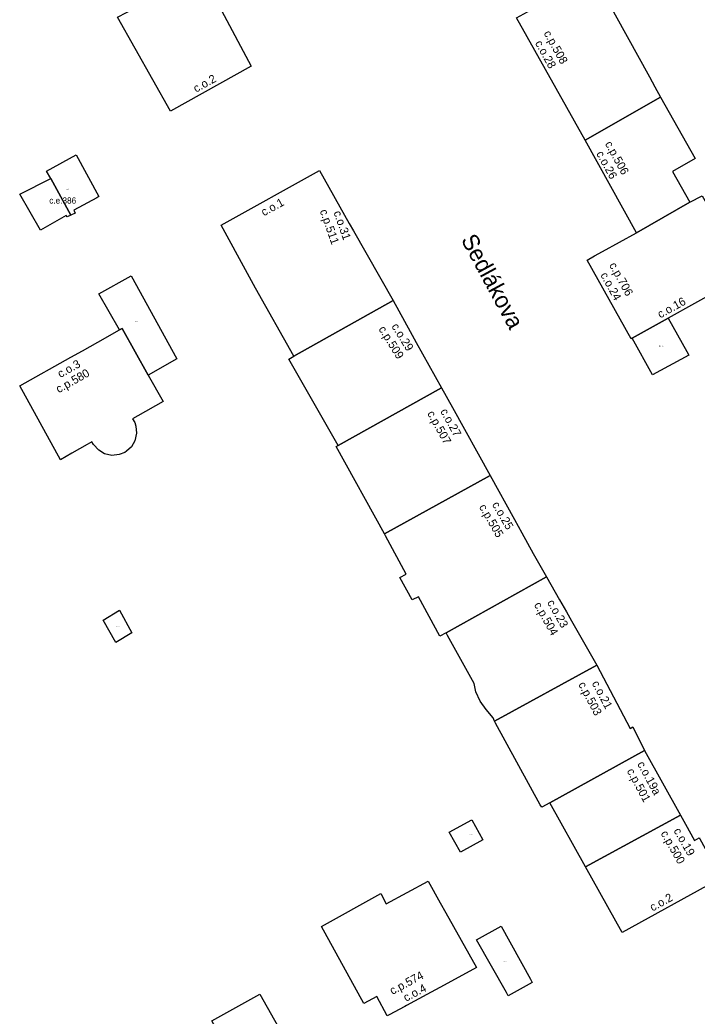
# Model space of a CAD drawing. Extents: x -600391 to -599491, y -1160176 to -1159402.
# Drawn here: x -600308.5 to -600226.8, y -1159941 to -1159820.9 of the extents above; entities that cross this region are included whole.
import ezdxf

# ---------------------------------------------------------------- set-up
doc = ezdxf.new("R2010")
doc.units = 0
for name, color, linetype in [('Level 10', 7, 'Continuous'), ('Level 11', 7, 'Continuous'), ('Level 12', 7, 'Continuous'), ('Level 23', 7, 'Continuous'), ('Level 24', 7, 'Continuous'), ('Level 25', 7, 'Continuous'), ('Level 61', 7, 'Continuous'), ('Level 62', 7, 'Continuous')]:
    doc.layers.add(name, color=color, linetype=linetype)

msp = doc.modelspace()

# ---------------------------------------------------------------- linework, layer by layer
at = {"layer": 'Level 61'}
for points in [[(-600237.94, -1159818), (-600232.57, -1159827.75)], [(-600284.2, -1159819.76), (-600280.6, -1159826.47)], [(-600290.35, -1159831.88), (-600296.72, -1159820.57)], [(-600240.34, -1159835.38), (-600248.62, -1159820.62)], [(-600280.6, -1159826.47), (-600290.35, -1159831.88)], [(-600232.57, -1159827.75), (-600231.9, -1159828.97)], [(-600231.9, -1159828.97), (-600231.22, -1159830.2)], [(-600240.34, -1159835.38), (-600231.22, -1159830.2)], [(-600231.22, -1159830.2), (-600240.34, -1159835.38)], [(-600231.22, -1159830.2), (-600227.07, -1159837.62)], [(-600234.14, -1159846.56), (-600240.34, -1159835.38)], [(-600305.31, -1159839.13), (-600301.74, -1159837.17)], [(-600301.74, -1159837.17), (-600298.98, -1159842.18)], [(-600227.07, -1159837.62), (-600229.77, -1159839.19)], [(-600304.8, -1159840.02), (-600305.31, -1159839.13)], [(-600284.24, -1159845.64), (-600272.36, -1159839.07)], [(-600272.36, -1159839.07), (-600268.78, -1159845.46)], [(-600308.51, -1159841.92), (-600304.8, -1159840.02)], [(-600304.8, -1159840.02), (-600302.38, -1159844.42)], [(-600302.38, -1159844.42), (-600304.8, -1159840.02)], [(-600229.77, -1159839.19), (-600227.68, -1159842.88)], [(-600306.03, -1159846.25), (-600308.51, -1159841.92)], [(-600299.25, -1159842.33), (-600302.02, -1159843.85)], [(-600298.98, -1159842.18), (-600299.25, -1159842.33)], [(-600227.68, -1159842.88), (-600226.21, -1159842.09)], [(-600302.02, -1159843.85), (-600301.86, -1159844.18)], [(-600227.68, -1159842.88), (-600234.14, -1159846.56)], [(-600234.14, -1159846.56), (-600227.68, -1159842.88)], [(-600302.92, -1159844.47), (-600305.73, -1159846.08)], [(-600302.81, -1159844.66), (-600302.92, -1159844.47)], [(-600302.38, -1159844.42), (-600302.81, -1159844.66)], [(-600301.86, -1159844.18), (-600302.38, -1159844.42)], [(-600305.73, -1159846.08), (-600306.03, -1159846.25)], [(-600281.06, -1159851.49), (-600284.24, -1159845.64)], [(-600268.78, -1159845.46), (-600268.28, -1159846.34)], [(-600268.28, -1159846.34), (-600263.49, -1159854.75)], [(-600238.23, -1159848.83), (-600234.14, -1159846.56)], [(-600240.09, -1159849.86), (-600239.19, -1159849.36)], [(-600234.77, -1159859.35), (-600240.09, -1159849.86)], [(-600239.19, -1159849.36), (-600238.23, -1159848.83)], [(-600298.99, -1159853.92), (-600295.08, -1159851.74)], [(-600295.08, -1159851.74), (-600289.57, -1159861.77)], [(-600280.09, -1159853.23), (-600281.06, -1159851.49)], [(-600220.78, -1159851.55), (-600230.3, -1159856.86)], [(-600275.48, -1159861.46), (-600280.09, -1159853.23)], [(-600296.48, -1159858.28), (-600298.99, -1159853.92)], [(-600263.49, -1159854.75), (-600275.48, -1159861.46)], [(-600275.48, -1159861.46), (-600263.49, -1159854.75)], [(-600263.49, -1159854.75), (-600261.42, -1159858.49)], [(-600234.65, -1159859.28), (-600230.3, -1159856.86)], [(-600230.3, -1159856.86), (-600234.65, -1159859.28)], [(-600230.3, -1159856.86), (-600228.06, -1159860.88)], [(-600299.11, -1159859.76), (-600296.48, -1159858.28)], [(-600296.48, -1159858.28), (-600296.16, -1159858.1)], [(-600296.16, -1159858.1), (-600296.48, -1159858.28)], [(-600296.16, -1159858.1), (-600293.02, -1159863.72)], [(-600293.02, -1159863.72), (-600296.16, -1159858.1)], [(-600261.42, -1159858.49), (-600260.69, -1159859.8)], [(-600234.65, -1159859.28), (-600234.77, -1159859.35)], [(-600232.19, -1159863.71), (-600234.65, -1159859.28)], [(-600302.35, -1159861.58), (-600300.95, -1159860.79)], [(-600300.95, -1159860.79), (-600299.11, -1159859.76)], [(-600260.69, -1159859.8), (-600257.67, -1159865.25)], [(-600308.51, -1159865.04), (-600302.35, -1159861.58)], [(-600289.57, -1159861.77), (-600293.02, -1159863.72)], [(-600276.06, -1159861.79), (-600275.48, -1159861.46)], [(-600270.12, -1159872.22), (-600276.06, -1159861.79)], [(-600227.82, -1159861.32), (-600232.19, -1159863.71)], [(-600228.06, -1159860.88), (-600227.82, -1159861.32)], [(-600293.02, -1159863.72), (-600291.24, -1159866.92)], [(-600303.63, -1159873.93), (-600308.51, -1159865.04)], [(-600270.12, -1159872.22), (-600257.67, -1159865.25)], [(-600257.67, -1159865.25), (-600270.12, -1159872.22)], [(-600257.67, -1159865.25), (-600256.34, -1159867.64)], [(-600291.24, -1159866.92), (-600294.28, -1159868.64)], [(-600256.34, -1159867.64), (-600251.8, -1159875.84)], [(-600294.28, -1159868.64), (-600294.91, -1159869)], [(-600294.91, -1159869), (-600294.66, -1159869.44)], [(-600294.66, -1159869.44), (-600294.51, -1159869.89)], [(-600294.51, -1159869.89), (-600294.43, -1159870.74)], [(-600294.43, -1159870.74), (-600294.63, -1159871.64)], [(-600300.38, -1159872.09), (-600302.25, -1159873.15)], [(-600299.82, -1159871.78), (-600300.38, -1159872.09)], [(-600299.65, -1159872.09), (-600299.82, -1159871.78)], [(-600298.98, -1159872.8), (-600299.65, -1159872.09)], [(-600298.3, -1159873.21), (-600298.98, -1159872.8)], [(-600295.06, -1159872.37), (-600295.66, -1159872.92)], [(-600294.63, -1159871.64), (-600295.06, -1159872.37)], [(-600270.35, -1159872.34), (-600270.12, -1159872.22)], [(-600264.54, -1159882.86), (-600270.35, -1159872.34)], [(-600302.25, -1159873.15), (-600303.63, -1159873.93)], [(-600297.44, -1159873.42), (-600298.3, -1159873.21)], [(-600296.54, -1159873.32), (-600297.44, -1159873.42)], [(-600295.86, -1159873.05), (-600296.54, -1159873.32)], [(-600295.66, -1159872.92), (-600295.86, -1159873.05)], [(-600264.54, -1159882.86), (-600251.8, -1159875.84)], [(-600251.8, -1159875.84), (-600264.54, -1159882.86)], [(-600251.8, -1159875.84), (-600248.85, -1159881.15)], [(-600248.85, -1159881.15), (-600247.96, -1159882.77)], [(-600264.39, -1159883.13), (-600264.54, -1159882.86)], [(-600261.92, -1159887.73), (-600264.39, -1159883.13)], [(-600247.96, -1159882.77), (-600246.6, -1159885.23)], [(-600246.6, -1159885.23), (-600244.97, -1159888.08)], [(-600262.68, -1159888.14), (-600261.92, -1159887.73)], [(-600261.19, -1159890.85), (-600262.68, -1159888.14)], [(-600244.97, -1159888.08), (-600257.09, -1159894.8)], [(-600257.09, -1159894.8), (-600244.97, -1159888.08)], [(-600244.97, -1159888.08), (-600243.41, -1159890.82)], [(-600260.44, -1159890.48), (-600261.19, -1159890.85)], [(-600257.87, -1159895.23), (-600260.44, -1159890.48)], [(-600243.41, -1159890.82), (-600242.59, -1159892.27)], [(-600298.48, -1159893.28), (-600296.49, -1159892.09)], [(-600296.49, -1159892.09), (-600295, -1159894.82)], [(-600242.59, -1159892.27), (-600241.96, -1159893.37)], [(-600296.94, -1159895.97), (-600298.48, -1159893.28)], [(-600241.96, -1159893.37), (-600238.92, -1159898.73)], [(-600295, -1159894.82), (-600296.94, -1159895.97)], [(-600257.09, -1159894.8), (-600257.87, -1159895.23)], [(-600256.91, -1159895.14), (-600257.09, -1159894.8)], [(-600253.73, -1159900.93), (-600256.91, -1159895.14)], [(-600251.25, -1159905.47), (-600238.92, -1159898.73)], [(-600238.92, -1159898.73), (-600251.25, -1159905.47)], [(-600238.92, -1159898.73), (-600234.91, -1159906.35)], [(-600253.52, -1159901.95), (-600253.73, -1159900.93)], [(-600252.99, -1159903.07), (-600253.52, -1159901.95)], [(-600252.25, -1159904.06), (-600252.99, -1159903.07)], [(-600251.43, -1159905.08), (-600252.25, -1159904.06)], [(-600251.25, -1159905.47), (-600251.43, -1159905.08)], [(-600251.13, -1159905.7), (-600251.25, -1159905.47)], [(-600245.73, -1159915.55), (-600251.13, -1159905.7)], [(-600234.91, -1159906.35), (-600234.58, -1159906.16)], [(-600234.58, -1159906.16), (-600233.17, -1159909.02)], [(-600244.58, -1159915.32), (-600233.17, -1159909.02)], [(-600233.17, -1159909.02), (-600244.58, -1159915.32)], [(-600233.17, -1159909.02), (-600228.82, -1159916.82)], [(-600245.56, -1159915.86), (-600245.73, -1159915.55)], [(-600244.58, -1159915.32), (-600245.56, -1159915.86)], [(-600240.29, -1159923.03), (-600244.58, -1159915.32)], [(-600228.82, -1159916.82), (-600240.29, -1159923.03)], [(-600240.29, -1159923.03), (-600228.82, -1159916.82)], [(-600228.82, -1159916.82), (-600228.23, -1159917.89)], [(-600256.71, -1159918.86), (-600253.99, -1159917.36)], [(-600253.99, -1159917.36), (-600252.66, -1159919.78)], [(-600228.23, -1159917.89), (-600227.14, -1159919.85)], [(-600255.38, -1159921.28), (-600256.71, -1159918.86)], [(-600227.14, -1159919.85), (-600226.57, -1159919.54)], [(-600252.66, -1159919.78), (-600255.38, -1159921.28)], [(-600235.87, -1159930.96), (-600240.29, -1159923.03)], [(-600264.32, -1159927.49), (-600259.28, -1159924.76)], [(-600259.28, -1159924.76), (-600257.8, -1159927.4)], [(-600224.48, -1159924.68), (-600235.87, -1159930.96)], [(-600272.11, -1159930.24), (-600264.96, -1159926.24)], [(-600264.96, -1159926.24), (-600264.32, -1159927.49)], [(-600257.8, -1159927.4), (-600257.13, -1159928.59)], [(-600257.13, -1159928.59), (-600253.42, -1159935.19)], [(-600267.03, -1159939.53), (-600272.11, -1159930.24)], [(-600253.42, -1159931.83), (-600250.47, -1159930.2)], [(-600250.47, -1159930.2), (-600246.93, -1159936.58)], [(-600249.83, -1159938.19), (-600253.42, -1159931.83)], [(-600253.42, -1159935.19), (-600257.32, -1159937.3)], [(-600257.32, -1159937.3), (-600259.41, -1159938.42)], [(-600246.71, -1159936.98), (-600249.6, -1159938.59)], [(-600246.93, -1159936.58), (-600246.71, -1159936.98)], [(-600285.36, -1159941.63), (-600279.55, -1159938.41)], [(-600279.55, -1159938.41), (-600274.78, -1159946.87)], [(-600265.47, -1159938.68), (-600267.03, -1159939.53)], [(-600264.2, -1159941.01), (-600265.47, -1159938.68)], [(-600259.41, -1159938.42), (-600261.86, -1159939.75)], [(-600249.6, -1159938.59), (-600249.83, -1159938.19)], [(-600262.09, -1159939.87), (-600263.95, -1159940.87)], [(-600261.86, -1159939.75), (-600262.09, -1159939.87)], [(-600263.95, -1159940.87), (-600264.2, -1159941.01)]]:
    msp.add_lwpolyline(points, dxfattribs=at)
at = {"layer": 'Level 62'}
for points in [[(-600288.29, -1159812.37), (-600286.39, -1159815.66), (-600284.2, -1159819.76), (-600280.6, -1159826.47), (-600290.35, -1159831.88), (-600296.72, -1159820.57), (-600294.57, -1159819.44), (-600296.16, -1159816.64), (-600288.29, -1159812.37)], [(-600231.22, -1159830.2), (-600240.34, -1159835.38), (-600248.62, -1159820.62), (-600239.3, -1159815.54), (-600238.62, -1159816.77), (-600237.94, -1159818), (-600232.57, -1159827.75), (-600231.9, -1159828.97), (-600231.22, -1159830.2)], [(-600227.68, -1159842.88), (-600234.14, -1159846.56), (-600240.34, -1159835.38), (-600231.22, -1159830.2), (-600227.07, -1159837.62), (-600229.77, -1159839.19), (-600227.68, -1159842.88)], [(-600299.25, -1159842.33), (-600302.02, -1159843.85), (-600301.86, -1159844.18), (-600302.38, -1159844.42), (-600304.8, -1159840.02), (-600305.31, -1159839.13), (-600301.74, -1159837.17), (-600298.98, -1159842.18), (-600299.25, -1159842.33)], [(-600281.06, -1159851.49), (-600284.24, -1159845.64), (-600272.36, -1159839.07), (-600268.78, -1159845.46), (-600268.28, -1159846.34), (-600263.49, -1159854.75), (-600275.48, -1159861.46), (-600280.09, -1159853.23), (-600281.06, -1159851.49)], [(-600304.8, -1159840.02), (-600302.38, -1159844.42), (-600302.81, -1159844.66), (-600302.92, -1159844.47), (-600305.73, -1159846.08), (-600306.03, -1159846.25), (-600308.51, -1159841.92), (-600304.8, -1159840.02)], [(-600238.23, -1159848.83), (-600234.14, -1159846.56), (-600227.68, -1159842.88), (-600226.21, -1159842.09), (-600220.78, -1159851.55), (-600230.3, -1159856.86), (-600234.65, -1159859.28), (-600234.77, -1159859.35), (-600240.09, -1159849.86), (-600239.19, -1159849.36), (-600238.23, -1159848.83)], [(-600295.08, -1159851.74), (-600289.57, -1159861.77), (-600293.02, -1159863.72), (-600296.16, -1159858.1), (-600296.48, -1159858.28), (-600298.99, -1159853.92), (-600295.08, -1159851.74)], [(-600270.12, -1159872.22), (-600276.06, -1159861.79), (-600275.48, -1159861.46), (-600263.49, -1159854.75), (-600261.42, -1159858.49), (-600260.69, -1159859.8), (-600257.67, -1159865.25), (-600270.12, -1159872.22)], [(-600232.19, -1159863.71), (-600234.65, -1159859.28), (-600230.3, -1159856.86), (-600228.06, -1159860.88), (-600227.82, -1159861.32), (-600232.19, -1159863.71)], [(-600300.95, -1159860.79), (-600299.11, -1159859.76), (-600296.48, -1159858.28), (-600296.16, -1159858.1), (-600293.02, -1159863.72), (-600291.24, -1159866.92), (-600294.28, -1159868.64), (-600294.91, -1159869), (-600294.66, -1159869.44), (-600294.51, -1159869.89), (-600294.43, -1159870.74), (-600294.63, -1159871.64), (-600295.06, -1159872.37), (-600295.66, -1159872.92), (-600295.86, -1159873.05), (-600296.54, -1159873.32), (-600297.44, -1159873.42), (-600298.3, -1159873.21), (-600298.98, -1159872.8), (-600299.65, -1159872.09), (-600299.82, -1159871.78), (-600300.38, -1159872.09), (-600302.25, -1159873.15), (-600303.63, -1159873.93), (-600308.51, -1159865.04), (-600302.35, -1159861.58), (-600300.95, -1159860.79)], [(-600270.12, -1159872.22), (-600257.67, -1159865.25), (-600256.34, -1159867.64), (-600251.8, -1159875.84), (-600264.54, -1159882.86), (-600270.35, -1159872.34), (-600270.12, -1159872.22)], [(-600264.54, -1159882.86), (-600251.8, -1159875.84), (-600248.85, -1159881.15), (-600247.96, -1159882.77), (-600246.6, -1159885.23), (-600244.97, -1159888.08), (-600257.09, -1159894.8), (-600257.87, -1159895.23), (-600260.44, -1159890.48), (-600261.19, -1159890.85), (-600262.68, -1159888.14), (-600261.92, -1159887.73), (-600264.39, -1159883.13), (-600264.54, -1159882.86)], [(-600241.96, -1159893.37), (-600238.92, -1159898.73), (-600251.25, -1159905.47), (-600251.43, -1159905.08), (-600252.25, -1159904.06), (-600252.99, -1159903.07), (-600253.52, -1159901.95), (-600253.73, -1159900.93), (-600256.91, -1159895.14), (-600257.09, -1159894.8), (-600244.97, -1159888.08), (-600243.41, -1159890.82), (-600242.59, -1159892.27), (-600241.96, -1159893.37)], [(-600298.48, -1159893.28), (-600296.49, -1159892.09), (-600295, -1159894.82), (-600296.94, -1159895.97), (-600298.48, -1159893.28)], [(-600238.92, -1159898.73), (-600234.91, -1159906.35), (-600234.58, -1159906.16), (-600233.17, -1159909.02), (-600244.58, -1159915.32), (-600245.56, -1159915.86), (-600245.73, -1159915.55), (-600251.13, -1159905.7), (-600251.25, -1159905.47), (-600238.92, -1159898.73)], [(-600244.58, -1159915.32), (-600233.17, -1159909.02), (-600228.82, -1159916.82), (-600240.29, -1159923.03), (-600244.58, -1159915.32)], [(-600224.36, -1159923.52), (-600224.22, -1159923.77), (-600224.78, -1159924.08), (-600224.48, -1159924.68), (-600235.87, -1159930.96), (-600240.29, -1159923.03), (-600228.82, -1159916.82), (-600228.23, -1159917.89), (-600227.14, -1159919.85), (-600226.57, -1159919.54), (-600226.5, -1159919.67), (-600224.36, -1159923.52)], [(-600255.38, -1159921.28), (-600256.71, -1159918.86), (-600253.99, -1159917.36), (-600252.66, -1159919.78), (-600255.38, -1159921.28)], [(-600253.42, -1159935.19), (-600257.32, -1159937.3), (-600259.41, -1159938.42), (-600261.86, -1159939.75), (-600262.09, -1159939.87), (-600263.95, -1159940.87), (-600264.2, -1159941.01), (-600265.47, -1159938.68), (-600267.03, -1159939.53), (-600272.11, -1159930.24), (-600264.96, -1159926.24), (-600264.32, -1159927.49), (-600259.28, -1159924.76), (-600257.8, -1159927.4), (-600257.13, -1159928.59), (-600253.42, -1159935.19)], [(-600246.93, -1159936.58), (-600246.71, -1159936.98), (-600249.6, -1159938.59), (-600249.83, -1159938.19), (-600253.42, -1159931.83), (-600250.47, -1159930.2), (-600246.93, -1159936.58)], [(-600285.36, -1159941.63), (-600279.55, -1159938.41), (-600274.78, -1159946.87), (-600275.98, -1159947.53), (-600279.95, -1159949.71), (-600280.65, -1159950.09), (-600285.36, -1159941.63)]]:
    msp.add_lwpolyline(points, dxfattribs=at)

# ---------------------------------------------------------------- texts
at = {"layer": 'Level 10'}
for s, rotation, p in [('c.o.28', 299.0307, (-600246.41, -1159823.68)), ('c.o.2', 29.0257, (-600287.26, -1159829.68)), ('c.o.26', 298.6589, (-600239.02, -1159837.01)), ('c.o.1', 28.7897, (-600279.08, -1159844.59)), ('c.o.31', 289.3174, (-600270.69, -1159844.1)), ('c.o.24', 298.6667, (-600238.52, -1159851.65)), ('c.o.16', 29.0641, (-600231.26, -1159856.91)), ('c.o.29', 301.8845, (-600263.73, -1159857.85)), ('c.o.3', 29.3206, (-600303.63, -1159864.1)), ('c.o.27', 298.7513, (-600257.83, -1159868.09)), ('c.o.25', 299.9595, (-600251.59, -1159879.33)), ('c.o.23', 299.3412, (-600244.95, -1159891.15)), ('c.o.21', 297.7695, (-600239.55, -1159900.89)), ('c.o.19a', 298.3462, (-600234.07, -1159910.63)), ('c.o.19', 299.6745, (-600229.69, -1159918.68)), ('c.o.2', 28.8693, (-600232.19, -1159928.44)), ('c.o.4', 27.8463, (-600261.93, -1159939.33))]:
    msp.add_text(s, height=1, rotation=rotation, dxfattribs=at).set_placement(p)
at = {"layer": 'Level 11'}
msp.add_text('Sedlákova', height=2, rotation=298.4605, dxfattribs=at).set_placement((-600255.35, -1159847.4))
at = {"layer": 'Level 12'}
for s, rotation, p in [('c.p.508', 299.0307, (-600245.36, -1159822.49)), ('c.p.506', 298.6589, (-600237.97, -1159835.83)), ('c.p.511', 289.3174, (-600272.35, -1159843.93)), ('c.p.706', 298.6667, (-600237.46, -1159850.46)), ('c.p.509', 301.8845, (-600265.29, -1159858.18)), ('c.p.580', 29.3206, (-600303.83, -1159865.93)), ('c.p.507', 298.7513, (-600259.41, -1159868.35)), ('c.p.505', 299.9595, (-600253.16, -1159879.63)), ('c.p.504', 299.3412, (-600246.53, -1159891.43)), ('c.p.503', 297.7695, (-600241.18, -1159901.03)), ('c.p.501', 298.3462, (-600235.33, -1159911.48)), ('c.p.500', 299.6745, (-600231.25, -1159919)), ('c.p.574', 27.8463, (-600263.58, -1159938.5))]:
    msp.add_text(s, height=1, rotation=rotation, dxfattribs=at).set_placement(p)
at = {"layer": 'Level 23'}
msp.add_text('c.e.386', height=0.74, dxfattribs=at).set_placement((-600304.97, -1159843.04))
at = {"layer": 'Level 24'}
for s, p in [('c.z.73', (-600302.97, -1159841.35)), ('c.z.209', (-600294.75, -1159857.34)), ('c.z.242', (-600296.87, -1159894.11)), ('c.z.262', (-600254.3, -1159919.21)), ('c.z.341', (-600250.23, -1159934.5))]:
    msp.add_text(s, height=0.1, dxfattribs=at).set_placement(p)
at = {"layer": 'Level 25'}
msp.add_text('c.pp.706_A', height=0.1, dxfattribs=at).set_placement((-600231.52, -1159860.26))

doc.saveas('drawing.dxf')
